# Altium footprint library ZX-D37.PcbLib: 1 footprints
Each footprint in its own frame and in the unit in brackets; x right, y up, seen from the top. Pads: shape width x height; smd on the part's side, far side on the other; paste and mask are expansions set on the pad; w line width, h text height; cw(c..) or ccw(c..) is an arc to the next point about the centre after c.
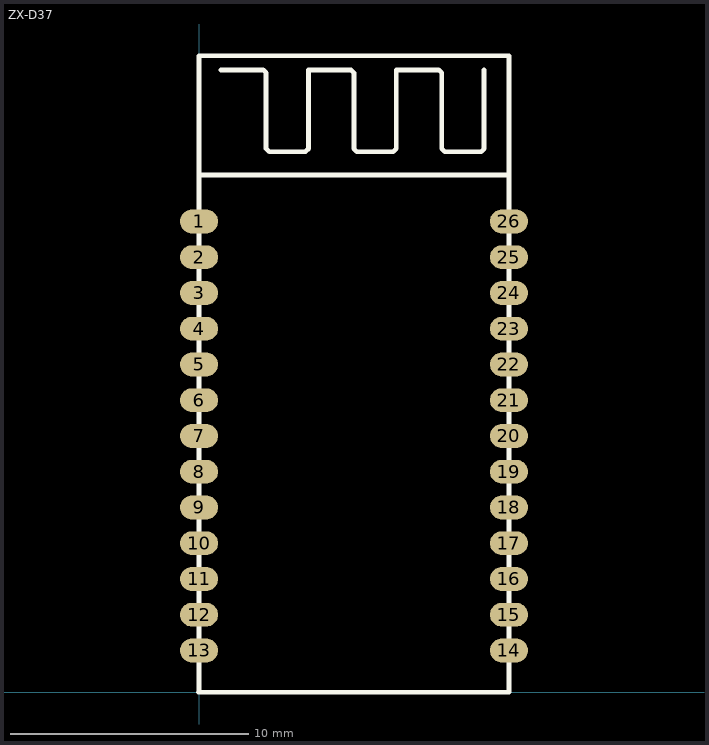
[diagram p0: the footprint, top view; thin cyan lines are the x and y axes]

## ZX-D37 [mm]
pads (26):
  oval 1.6x1 smd: 1(0,19.75) 2(0,18.25) 3(0,16.75) 4(0,15.25) 5(0,13.75) 6(0,12.25) 7(0,10.75) 8(0,9.25) 9(0,7.75) 10(0,6.25) 11(0,4.75) 12(0,3.25) 13(0,1.75) 14(13,1.75) 15(13,3.25) 16(13,4.75) 17(13,6.25) 18(13,7.75) 19(13,9.25) 20(13,10.75) 21(13,12.25) 22(13,13.75) 23(13,15.25) 24(13,16.75) 25(13,18.25) 26(13,19.75)
Top Overlay:
  lines w0.2: -0.027,0 13,0 13,26.7 0,26.7 0,0 ; 0,21.7 13,21.7 ; 0.908,26.108 2.686,26.108 2.813,25.981 2.813,22.806 2.94,22.679 4.464,22.679 4.591,22.806 4.591,26.108 6.369,26.108 6.496,25.981 6.496,22.806 6.623,22.679 8.147,22.679 8.274,22.806 8.274,26.108 10.052,26.108 10.179,25.981 10.179,22.806 10.306,22.679 11.83,22.679 11.957,22.806 11.957,26.108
